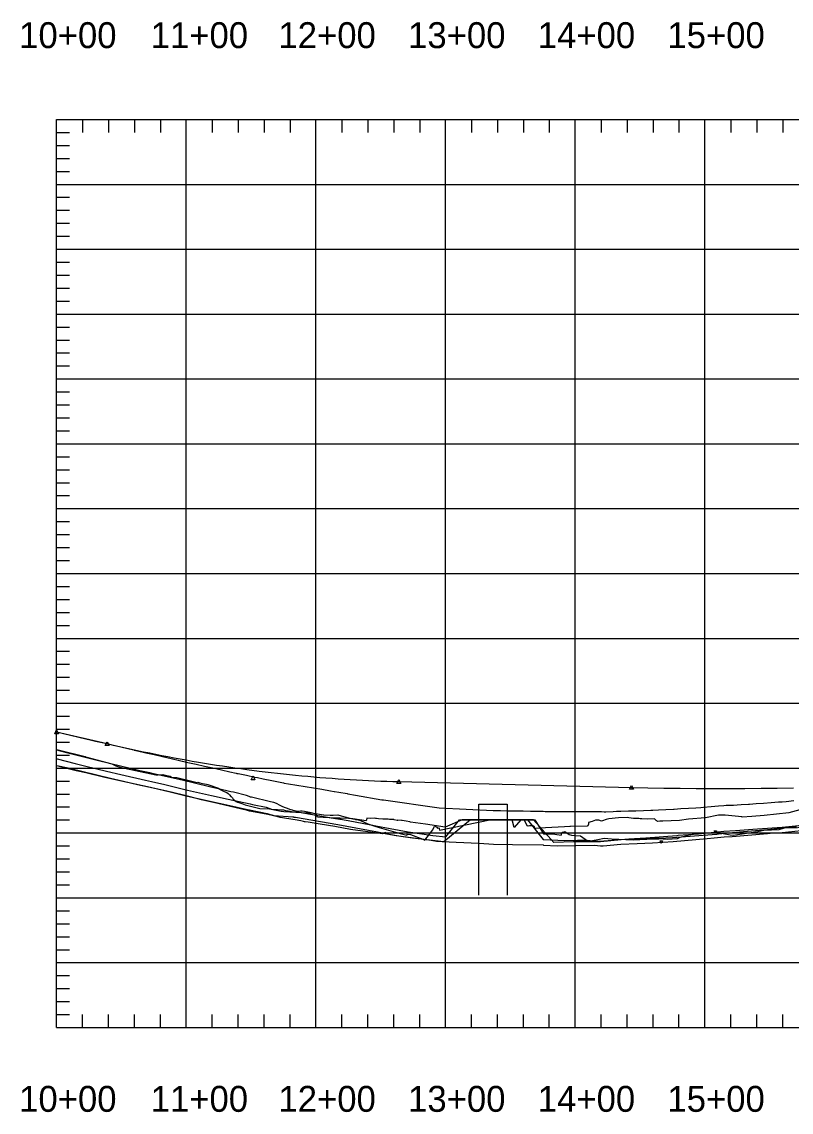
# Model space of a CAD drawing. Extents: x 704797 to 712284, y 374940 to 376945.
# Drawn here: x 708107 to 708700, y 375160 to 376001 of the extents above; entities that cross this region are included whole.
import ezdxf

# ---------------------------------------------------------------- set-up
doc = ezdxf.new("R2010")
doc.units = 0
for name, color, linetype in [('10', 7, 'Continuous'), ('12', 7, 'Continuous'), ('13', 7, 'Continuous'), ('48', 7, 'Continuous'), ('59', 7, 'Continuous'), ('61', 7, 'Continuous'), ('Existing', 7, 'Continuous')]:
    doc.layers.add(name, color=color, linetype=linetype)

msp = doc.modelspace()

# ---------------------------------------------------------------- linework, layer by layer
for points in [[(708133.69, 375454.97), (708135.19, 375451.97), (708132.19, 375451.97)], [(708172.67, 375445.81), (708174.17, 375442.81), (708171.17, 375442.81)], [(708285.17, 375419.37), (708286.67, 375416.37), (708283.67, 375416.37)], [(708397.67, 375416.56), (708399.17, 375413.56), (708396.17, 375413.56)], [(708577.04, 375412.08), (708578.54, 375409.08), (708575.54, 375409.08)]]:
    msp.add_lwpolyline(points, close=True)
at = {"layer": '10'}
for points in [[(708133.69, 375439.73), (708134.76, 375439.47), (708155.61, 375434.31), (708155.61, 375434.31), (708155.66, 375434.3), (708155.98, 375434.22), (708176.28, 375428.84), (708179.34, 375427.13), (708182.39, 375426.07), (708210.14, 375420.26), (708212.04, 375420.15), (708215.59, 375420.47), (708216.24, 375420.32), (708221.15, 375419.28), (708222.3, 375418.47), (708226.34, 375418.16), (708241.94, 375414.47), (708242.59, 375414.52), (708244.15, 375414), (708246.24, 375413.5), (708249.33, 375413.04), (708250.42, 375412.8), (708258.47, 375409.87), (708259.35, 375409.33), (708260.9, 375408.42), (708262.5, 375407.6), (708264.18, 375406.83), (708265, 375406.52), (708265.94, 375405.83), (708265.94, 375405.82), (708266.94, 375404.86), (708267.07, 375404.74), (708268.06, 375403.67), (708268.24, 375403.5), (708269.22, 375402.41), (708269.93, 375401.6), (708270.55, 375401.03), (708271.12, 375400.42), (708272.09, 375399.6), (708272.69, 375399.44), (708273.08, 375399.27), (708273.51, 375399.08), (708276.41, 375398.04), (708279.06, 375397.06), (708290.46, 375394.38), (708297.87, 375394.05), (708306.84, 375392.26), (708307.08, 375392.18), (708307.81, 375392.17), (708308.97, 375391.99), (708331.72, 375390.71), (708339.62, 375389.37), (708339.71, 375389.36), (708344.75, 375389.22), (708346.96, 375389.15), (708350.63, 375389.48), (708353.13, 375388.72), (708362.08, 375386.4), (708362.97, 375386.23), (708363.62, 375385.96), (708364.13, 375385.85), (708365.14, 375385.7), (708366.17, 375385.46), (708367.97, 375385.13), (708373.67, 375382.49), (708379.22, 375380.66), (708382.55, 375379.59), (708394.93, 375376.12), (708399.74, 375374.83), (708403.87, 375373.68), (708404.35, 375374.46), (708406.66, 375374.26), (708416.18, 375370.6), (708417.75, 375369.99), (708423.72, 375377.78), (708425.07, 375380.6), (708427.06, 375379.94), (708427.24, 375379.04), (708428.49, 375379.28), (708428.63, 375379.15), (708428.73, 375378.94), (708428.88, 375377.56), (708467.92, 375385.47), (708502.56, 375385.47), (708509.27, 375374.88), (708518.03, 375374.57), (708522.92, 375373.81), (708523.34, 375375.43), (708523.77, 375376.13), (708524.36, 375376.02), (708525.71, 375376.64), (708528.99, 375374.37), (708530.85, 375373.63), (708533.58, 375373.54), (708537.78, 375373.12), (708543.02, 375369.34), (708546.99, 375369.68), (708551.22, 375370.29), (708556.01, 375371.41), (708561.7, 375370.97), (708578.43, 375370.22), (708589, 375370.55), (708598.16, 375371.04), (708598.39, 375371.05), (708604.7, 375370.79), (708612.65, 375371.23), (708614.53, 375372.14), (708623.8, 375374.49), (708627.82, 375374.94), (708643.39, 375376.09), (708647.69, 375375.08), (708653.26, 375373.97), (708655.37, 375373.74), (708674.49, 375376.61), (708679.08, 375377.54), (708691.09, 375378.17), (708695.19, 375379.52), (708715.38, 375379.96)], [(708715.31, 375395.49), (708698.44, 375391.04), (708679.27, 375388.8), (708669.77, 375388.06), (708662.47, 375387.69), (708662.05, 375387.83), (708649.33, 375389.29), (708645.46, 375389.29), (708644.75, 375389.2), (708644.28, 375389.12), (708634.22, 375387.2), (708621.16, 375386), (708614.04, 375385.15), (708601.26, 375384.58), (708599.05, 375384.46), (708597.12, 375384.35), (708596.73, 375384.68), (708596.17, 375385.04), (708595.73, 375385.27), (708594.9, 375386.27), (708589.46, 375386.18), (708589.43, 375386.18), (708585.05, 375386.37), (708583.67, 375386.45), (708582.63, 375386.49), (708579.54, 375386.55), (708578.61, 375386.54), (708575.1, 375387.21), (708574.98, 375387.2), (708574.08, 375387.29), (708567.06, 375387.06), (708566.99, 375387.03), (708559.61, 375386.34), (708557.61, 375385.77), (708554.7, 375384.86), (708553.84, 375384.6), (708551.96, 375385.43), (708549.23, 375385.21), (708546.67, 375384.34), (708544, 375383.42), (708543.78, 375382.31), (708543.49, 375380.83), (708542.9, 375380.62), (708530.03, 375380.32), (708529.52, 375380.31), (708525.52, 375380.18), (708505.77, 375379.09), (708503.24, 375379.01), (708502.6, 375379.26), (708502.55, 375379.27), (708502.25, 375380.16), (708501.76, 375380.78), (708500.3, 375380.84), (708498.9, 375380.87), (708498.47, 375380.88), (708497.45, 375380.69), (708496.86, 375380.59), (708494.26, 375385.47), (708493.75, 375385.47), (708493.25, 375385.47), (708492.78, 375385.47), (708492.44, 375385.47), (708492.34, 375385.47), (708491.68, 375385.47), (708486.45, 375379.69), (708485.13, 375385.47), (708483.66, 375385.47), (708482.96, 375385.47), (708482.26, 375385.47), (708480.13, 375385.47), (708470.9, 375385.47), (708456.29, 375385.47), (708446.43, 375385.47), (708433.3, 375379.83), (708433.25, 375379.82), (708418.07, 375382.11), (708406.74, 375383.82), (708406.15, 375383.91), (708403.38, 375384.42), (708400.09, 375384.97), (708400, 375384.99), (708399.76, 375385.03), (708396.81, 375385.31), (708396.58, 375385.14), (708396.43, 375385.14), (708394.07, 375385.69), (708393.71, 375385.72), (708393.44, 375385.76), (708390.68, 375385.91), (708390.55, 375385.93), (708390.46, 375385.95), (708389.51, 375386.03), (708389.13, 375386.03), (708387.57, 375386.05), (708387.45, 375386.05), (708385.39, 375386.05), (708381.97, 375386.37), (708380.38, 375386.55), (708379.49, 375386.63), (708378.62, 375386.78), (708376.1, 375386.6), (708375.92, 375386.6), (708372.99, 375386.96), (708372.65, 375385.69), (708372.38, 375384.87), (708362.14, 375386.21), (708358.85, 375386.64), (708352.06, 375386.79), (708351.39, 375386.77), (708350.46, 375386.78), (708349.16, 375386.82), (708347.25, 375386.89), (708344.31, 375387.03), (708339.31, 375387.29), (708334.89, 375387.52), (708334.62, 375388.13), (708334.28, 375388.77), (708333.82, 375390.04), (708330.06, 375390.91), (708324.8, 375391.95), (708322.97, 375392.16), (708322.11, 375392.14), (708321.78, 375392.13), (708319.48, 375391.97), (708318.95, 375392.08), (708318.43, 375392.25), (708316.24, 375392.79), (708315.64, 375393), (708313.61, 375393.57), (708312.96, 375393.83), (708310.97, 375394.47), (708310.31, 375394.74), (708308.26, 375395.63), (708305.98, 375396.73), (708303.19, 375398.21), (708301.32, 375399.02), (708298.67, 375399.56), (708284.03, 375402.92), (708283.25, 375403.16), (708282.26, 375403.52), (708280.09, 375404.24), (708270, 375406.78), (708268.14, 375407.19), (708264.91, 375407.85), (708260.58, 375408.88), (708251.7, 375411.01), (708230.55, 375416.13), (708208.39, 375421.03), (708205.55, 375421.7), (708197.84, 375423.44), (708175.57, 375428.71), (708163.96, 375431.67), (708142.32, 375437.07), (708134.39, 375438.99)]]:
    msp.add_lwpolyline(points, dxfattribs=at)
at = {"layer": '12'}
for points in [[(708133.69, 375432.68), (708134.02, 375432.59), (708148.08, 375428.91), (708156.15, 375426.96), (708172.11, 375423.11), (708183.26, 375420.44), (708202.2, 375416.19), (708206.78, 375415.19), (708217.25, 375412.76), (708234.55, 375408.41), (708253.22, 375404.37), (708265.87, 375401.49), (708282.9, 375398), (708284.83, 375397.5), (708295.34, 375395.24), (708297.44, 375394.55), (708299.44, 375393.84), (708299.66, 375393.82), (708308.6, 375393.21), (708310.14, 375392.84), (708311.33, 375392.61), (708312.34, 375392.45), (708313.2, 375392.31), (708313.91, 375392.18), (708314.5, 375392.04), (708320.64, 375391.6), (708345.42, 375387.16), (708350.63, 375386.4), (708351.32, 375386.31), (708352.13, 375386.2), (708353.08, 375386.06), (708354.17, 375385.88), (708355.47, 375385.66), (708356.95, 375385.39), (708358.65, 375385.07), (708376.14, 375381.72), (708377.68, 375381.44), (708379.84, 375381.03), (708390.95, 375378.92), (708404.72, 375376.29), (708415.31, 375374.83), (708423.93, 375373.56), (708433.76, 375372.55), (708444.47, 375385.47), (708445.33, 375385.47), (708468.35, 375385.47), (708470.13, 375385.47), (708496.9, 375385.47), (708509.01, 375370.49), (708509.22, 375370.32), (708525.68, 375369.67), (708535.51, 375369.87), (708542.67, 375369.91), (708542.81, 375369.91), (708549.73, 375369.2), (708552.77, 375369.13), (708575.08, 375370.92), (708588, 375371.61), (708612.07, 375373.53), (708612.99, 375373.62), (708628.75, 375374.81), (708648.3, 375376.79), (708657.22, 375377.28), (708670.59, 375378.5), (708674.2, 375378.72), (708693.31, 375380.02), (708716.04, 375382.23)], [(708133.69, 375427.41), (708148.65, 375423.72), (708156.15, 375421.96), (708170.91, 375418.5), (708184.72, 375415.29), (708203.76, 375411.15), (708220.29, 375407.32), (708233.71, 375403.95), (708248.56, 375400.73), (708267.15, 375396.49), (708280.97, 375393.65), (708282.56, 375393.24), (708296.05, 375390.33), (708297.61, 375390.02), (708299.55, 375389.44), (708301.32, 375388.87), (708315.75, 375387.9), (708316.05, 375387.84), (708316.28, 375387.79), (708316.47, 375387.77), (708316.63, 375387.74), (708316.76, 375387.72), (708316.86, 375387.7), (708317.91, 375387.63), (708350.44, 375382.01), (708350.52, 375382), (708350.53, 375382), (708350.54, 375382), (708350.56, 375382), (708350.57, 375381.99), (708350.59, 375381.99), (708350.61, 375381.99), (708350.63, 375381.98), (708381.27, 375376.22), (708382.41, 375376), (708388.27, 375374.9), (708395.49, 375373.52), (708422.66, 375369.78), (708426.55, 375369.21), (708430.96, 375368.76), (708441.77, 375368.35), (708459.24, 375367.49), (708459.57, 375367.47), (708470.52, 375366.92), (708485.24, 375366.56), (708509, 375366.22), (708509.12, 375366.12), (708519.62, 375365.63), (708548.44, 375365.95), (708548.54, 375365.95), (708553.12, 375365.52), (708555.09, 375365.49), (708568.92, 375366.69), (708581.41, 375367.43), (708593.17, 375367.87), (708609.3, 375368.92), (708635.35, 375371.06), (708640.95, 375371.66), (708648.48, 375372.38), (708654.71, 375372.69), (708682, 375375.01), (708683.97, 375375.19), (708693.32, 375375.9), (708708.03, 375377.45)]]:
    msp.add_lwpolyline(points, dxfattribs=at)
for points in [[(708641.73, 375375.12), (708640.73, 375377.12), (708642.73, 375377.12)], [(708600.06, 375367.32), (708599.06, 375369.32), (708601.06, 375369.32)]]:
    msp.add_lwpolyline(points, close=True, dxfattribs=at)
at = {"layer": '13'}
msp.add_lwpolyline([(708704.38, 375380.21), (708689.31, 375378.72), (708682.01, 375377.86), (708660.47, 375376.08), (708644.16, 375374.53), (708642.99, 375374.33), (708632.24, 375373.45), (708608.63, 375371.72), (708598.12, 375371.25), (708595.67, 375371.27), (708595.53, 375371.32), (708590.46, 375371.13), (708583.47, 375370.8), (708569.07, 375370.17), (708553.09, 375368.63), (708549.99, 375368.62), (708532.43, 375368.5), (708517.04, 375368.09), (708501.37, 375385.47), (708493.22, 375385.47), (708484.06, 375385.47), (708479.9, 375385.47), (708478.58, 375385.47), (708473.17, 375385.47), (708461.25, 375385.47), (708452.91, 375385.47), (708432.27, 375368.56), (708408.28, 375371.35), (708399.09, 375372.68), (708390.07, 375374.27), (708387.12, 375375.77), (708384.97, 375374.75), (708383.3, 375374.92), (708360.4, 375378.22), (708348.14, 375380.39), (708336.94, 375382.32), (708327.72, 375383.68), (708325.46, 375383.96), (708324.88, 375384.12), (708324.14, 375384.29), (708323.14, 375384.49), (708321.9, 375384.74), (708320.54, 375385), (708319.16, 375385.28), (708309.37, 375386.78), (708307.81, 375387.13), (708306.15, 375387.49), (708304.36, 375387.88), (708296.49, 375389.61), (708284.04, 375392.04), (708282.49, 375392.22), (708280.87, 375392.65), (708263.53, 375396.86), (708258.09, 375398.21), (708245.51, 375400.97), (708242.67, 375401.7), (708240.48, 375402.26), (708235.54, 375403.53), (708230.43, 375404.8), (708218.65, 375407.56), (708208.21, 375409.9), (708196.14, 375412.65), (708185.25, 375415.24), (708175.23, 375417.54), (708164.63, 375420.1), (708153.21, 375422.78), (708145.66, 375424.55), (708142.6, 375425.27), (708133.88, 375427.31)], dxfattribs=at)
at = {"layer": '48'}
for p, q in [((708133.69, 375453.47), (708172.67, 375444.31)), ((708397.67, 375415.06), (708577.04, 375410.58))]:
    msp.add_line(p, q, dxfattribs=at)
for points in [[(708172.67, 375444.31), (708177.36, 375443.22), (708182.05, 375442.15), (708186.73, 375441.1), (708191.42, 375440.07), (708196.11, 375439.06), (708200.8, 375438.07), (708205.48, 375437.1), (708210.17, 375436.15), (708214.86, 375435.23), (708219.55, 375434.32), (708224.23, 375433.43), (708228.92, 375432.57), (708233.61, 375431.72), (708238.3, 375430.9), (708242.98, 375430.09), (708247.67, 375429.31), (708252.36, 375428.55), (708257.05, 375427.8), (708261.73, 375427.08), (708266.42, 375426.38), (708271.11, 375425.7), (708275.8, 375425.04), (708280.48, 375424.4), (708289.86, 375423.18), (708294.55, 375422.6), (708299.23, 375422.04), (708303.92, 375421.51), (708308.61, 375420.99), (708313.3, 375420.49), (708317.98, 375420.02), (708322.67, 375419.56), (708327.36, 375419.12), (708332.05, 375418.71), (708336.73, 375418.32), (708341.42, 375417.94), (708346.11, 375417.59), (708350.8, 375417.26), (708355.48, 375416.95), (708360.17, 375416.65), (708364.86, 375416.38), (708369.55, 375416.13), (708374.23, 375415.9), (708378.92, 375415.69), (708383.61, 375415.5), (708388.3, 375415.34), (708392.98, 375415.19), (708397.67, 375415.06)], [(708577.04, 375410.58), (708589.54, 375410.29), (708602.04, 375410.06), (708614.54, 375409.89), (708627.04, 375409.78), (708639.54, 375409.72), (708652.04, 375409.72), (708664.54, 375409.77), (708677.04, 375409.88), (708689.54, 375410.05), (708702.04, 375410.27)]]:
    msp.add_lwpolyline(points, dxfattribs=at)
at = {"layer": '59'}
msp.add_lwpolyline([(708459.24, 375327.55), (708459.25, 375379.33), (708459.26, 375397.55), (708468.78, 375397.63), (708470.26, 375397.65), (708470.29, 375397.65), (708476.09, 375397.59), (708477.63, 375397.58), (708480.65, 375397.55), (708481.27, 375397.55), (708481.27, 375392.88), (708481.29, 375327.55)], dxfattribs=at)
at = {"layer": '61'}
for p, q in [((708133.69, 375925.47), (712133.69, 375925.47)), ((708133.69, 375225.47), (708133.69, 375925.47)), ((708153.69, 375925.47), (708153.69, 375915.47)), ((708173.69, 375925.47), (708173.69, 375915.47)), ((708193.69, 375925.47), (708193.69, 375915.47)), ((708213.69, 375925.47), (708213.69, 375915.47)), ((708233.69, 375225.47), (708233.69, 375925.47)), ((708253.69, 375925.47), (708253.69, 375915.47)), ((708273.69, 375925.47), (708273.69, 375915.47)), ((708293.69, 375925.47), (708293.69, 375915.47)), ((708313.69, 375925.47), (708313.69, 375915.47)), ((708333.69, 375225.47), (708333.69, 375925.47)), ((708353.69, 375925.47), (708353.69, 375915.47)), ((708373.69, 375925.47), (708373.69, 375915.47)), ((708393.69, 375925.47), (708393.69, 375915.47)), ((708413.69, 375925.47), (708413.69, 375915.47)), ((708433.69, 375225.47), (708433.69, 375925.47)), ((708453.69, 375925.47), (708453.69, 375915.47)), ((708473.69, 375925.47), (708473.69, 375915.47)), ((708493.69, 375925.47), (708493.69, 375915.47)), ((708513.69, 375925.47), (708513.69, 375915.47)), ((708533.69, 375225.47), (708533.69, 375925.47)), ((708553.69, 375925.47), (708553.69, 375915.47)), ((708573.69, 375925.47), (708573.69, 375915.47)), ((708593.69, 375925.47), (708593.69, 375915.47)), ((708613.69, 375925.47), (708613.69, 375915.47)), ((708633.69, 375225.47), (708633.69, 375925.47)), ((708653.69, 375925.47), (708653.69, 375915.47)), ((708673.69, 375925.47), (708673.69, 375915.47)), ((708693.69, 375925.47), (708693.69, 375915.47)), ((708133.69, 375915.47), (708143.69, 375915.47)), ((708133.69, 375905.47), (708143.69, 375905.47)), ((708133.69, 375895.47), (708143.69, 375895.47)), ((708133.69, 375885.47), (708143.69, 375885.47)), ((708133.69, 375875.47), (712133.69, 375875.47)), ((708133.69, 375865.47), (708143.69, 375865.47)), ((708133.69, 375855.47), (708143.69, 375855.47)), ((708133.69, 375845.47), (708143.69, 375845.47)), ((708133.69, 375835.47), (708143.69, 375835.47)), ((708133.69, 375825.47), (712133.69, 375825.47)), ((708133.69, 375815.47), (708143.69, 375815.47)), ((708133.69, 375805.47), (708143.69, 375805.47)), ((708133.69, 375795.47), (708143.69, 375795.47)), ((708133.69, 375785.47), (708143.69, 375785.47)), ((708133.69, 375775.47), (712133.69, 375775.47)), ((708133.69, 375765.47), (708143.69, 375765.47)), ((708133.69, 375755.47), (708143.69, 375755.47)), ((708133.69, 375745.47), (708143.69, 375745.47)), ((708133.69, 375735.47), (708143.69, 375735.47)), ((708133.69, 375725.47), (712133.69, 375725.47)), ((708133.69, 375715.47), (708143.69, 375715.47)), ((708133.69, 375705.47), (708143.69, 375705.47)), ((708133.69, 375695.47), (708143.69, 375695.47)), ((708133.69, 375685.47), (708143.69, 375685.47)), ((708133.69, 375675.47), (712133.69, 375675.47)), ((708133.69, 375665.47), (708143.69, 375665.47)), ((708133.69, 375655.47), (708143.69, 375655.47)), ((708133.69, 375645.47), (708143.69, 375645.47)), ((708133.69, 375635.47), (708143.69, 375635.47)), ((708133.69, 375625.47), (712133.69, 375625.47)), ((708133.69, 375615.47), (708143.69, 375615.47)), ((708133.69, 375605.47), (708143.69, 375605.47)), ((708133.69, 375595.47), (708143.69, 375595.47)), ((708133.69, 375585.47), (708143.69, 375585.47)), ((708133.69, 375575.47), (712133.69, 375575.47)), ((708133.69, 375565.47), (708143.69, 375565.47)), ((708133.69, 375555.47), (708143.69, 375555.47)), ((708133.69, 375545.47), (708143.69, 375545.47)), ((708133.69, 375535.47), (708143.69, 375535.47)), ((708133.69, 375525.47), (712133.69, 375525.47)), ((708133.69, 375515.47), (708143.69, 375515.47)), ((708133.69, 375505.47), (708143.69, 375505.47)), ((708133.69, 375495.47), (708143.69, 375495.47)), ((708133.69, 375485.47), (708143.69, 375485.47)), ((708133.69, 375475.47), (712133.69, 375475.47)), ((708133.69, 375465.47), (708143.69, 375465.47)), ((708133.69, 375455.47), (708143.69, 375455.47)), ((708133.69, 375445.47), (708143.69, 375445.47)), ((708133.69, 375435.47), (708143.69, 375435.47)), ((708133.69, 375425.47), (712133.69, 375425.47)), ((708133.69, 375415.47), (708143.69, 375415.47)), ((708133.69, 375405.47), (708143.69, 375405.47)), ((708133.69, 375395.47), (708143.69, 375395.47)), ((708133.69, 375385.47), (708143.69, 375385.47)), ((708133.69, 375375.47), (712133.69, 375375.47)), ((708133.69, 375365.47), (708143.69, 375365.47)), ((708133.69, 375355.47), (708143.69, 375355.47)), ((708133.69, 375345.47), (708143.69, 375345.47)), ((708133.69, 375335.47), (708143.69, 375335.47)), ((708133.69, 375325.47), (712133.69, 375325.47)), ((708133.69, 375315.47), (708143.69, 375315.47)), ((708133.69, 375305.47), (708143.69, 375305.47)), ((708133.69, 375295.47), (708143.69, 375295.47)), ((708133.69, 375285.47), (708143.69, 375285.47)), ((708133.69, 375275.47), (712133.69, 375275.47)), ((708133.69, 375265.47), (708143.69, 375265.47)), ((708133.69, 375255.47), (708143.69, 375255.47)), ((708133.69, 375245.47), (708143.69, 375245.47)), ((708133.69, 375235.47), (708143.69, 375235.47)), ((708153.69, 375225.47), (708153.69, 375235.47)), ((708173.69, 375225.47), (708173.69, 375235.47)), ((708193.69, 375225.47), (708193.69, 375235.47)), ((708213.69, 375225.47), (708213.69, 375235.47)), ((708253.69, 375225.47), (708253.69, 375235.47)), ((708273.69, 375225.47), (708273.69, 375235.47)), ((708293.69, 375225.47), (708293.69, 375235.47)), ((708313.69, 375225.47), (708313.69, 375235.47)), ((708353.69, 375225.47), (708353.69, 375235.47)), ((708373.69, 375225.47), (708373.69, 375235.47)), ((708393.69, 375225.47), (708393.69, 375235.47)), ((708413.69, 375225.47), (708413.69, 375235.47)), ((708453.69, 375225.47), (708453.69, 375235.47)), ((708473.69, 375225.47), (708473.69, 375235.47)), ((708493.69, 375225.47), (708493.69, 375235.47)), ((708513.69, 375225.47), (708513.69, 375235.47)), ((708553.69, 375225.47), (708553.69, 375235.47)), ((708573.69, 375225.47), (708573.69, 375235.47)), ((708593.69, 375225.47), (708593.69, 375235.47)), ((708613.69, 375225.47), (708613.69, 375235.47)), ((708653.69, 375225.47), (708653.69, 375235.47)), ((708673.69, 375225.47), (708673.69, 375235.47)), ((708693.69, 375225.47), (708693.69, 375235.47)), ((708133.69, 375225.47), (712133.69, 375225.47))]:
    msp.add_line(p, q, dxfattribs=at)
at = {"layer": 'Existing'}
msp.add_lwpolyline([(708133.69, 375453.38), (708144.27, 375450.89), (708150.74, 375449.36), (708157.21, 375447.83), (708157.39, 375447.79), (708157.44, 375447.77), (708157.48, 375447.76), (708163.67, 375446.32), (708170.13, 375444.82), (708170.14, 375444.82), (708170.17, 375444.81), (708176.61, 375443.31), (708183.08, 375441.8), (708189.55, 375440.29), (708193.14, 375439.45), (708193.28, 375439.42), (708193.43, 375439.38), (708196.02, 375438.79), (708202.49, 375437.31), (708208.96, 375435.83), (708215.43, 375434.34), (708221.9, 375432.85), (708228.37, 375431.36), (708230.52, 375430.87), (708230.67, 375430.83), (708230.74, 375430.81), (708230.81, 375430.8), (708230.87, 375430.78), (708234.84, 375429.89), (708241.31, 375428.45), (708247.77, 375427), (708254.24, 375425.55), (708260.71, 375424.09), (708267.18, 375422.64), (708272.08, 375421.53), (708272.22, 375421.49), (708272.66, 375421.38), (708272.7, 375421.37), (708272.74, 375421.37), (708273.65, 375421.18), (708280.12, 375419.88), (708286.59, 375418.56), (708288.61, 375418.15), (708293.06, 375417.23), (708299.53, 375415.89), (708306, 375414.55), (708308.7, 375413.99), (708308.73, 375413.98), (708308.76, 375413.97), (708309.05, 375413.95), (708312.47, 375413.39), (708318.94, 375412.32), (708325.41, 375411.24), (708331.87, 375410.17), (708338.34, 375409.1), (708344.81, 375408.03), (708347.85, 375407.52), (708348.05, 375407.49), (708351.28, 375406.92), (708357.75, 375405.79), (708358.29, 375405.7), (708364.22, 375404.65), (708384.6, 375401.04), (708385.24, 375400.95), (708385.28, 375400.95), (708385.34, 375400.97), (708385.42, 375400.93), (708385.66, 375400.89), (708428.69, 375394.74), (708470.29, 375392.8), (708470.92, 375392.77), (708470.92, 375392.77), (708470.92, 375392.77), (708470.92, 375392.77), (708476.09, 375392.71), (708481.88, 375392.63), (708487.68, 375392.55), (708493.48, 375392.46), (708499.27, 375392.37), (708505.07, 375392.26), (708508.99, 375392.19), (708509, 375392.18), (708510.53, 375392.1), (708510.87, 375392.1), (708516.66, 375392.11), (708522.46, 375392.11), (708528.26, 375392.11), (708534.05, 375392.09), (708539.85, 375392.06), (708545.65, 375392.01), (708551.44, 375391.96), (708553.83, 375391.94), (708553.87, 375391.94), (708556.01, 375391.66), (708556.99, 375391.61), (708557.24, 375391.63), (708563.04, 375391.98), (708565.51, 375392.12), (708568.83, 375392.23), (708574.63, 375392.42), (708580.43, 375392.6), (708586.22, 375392.77), (708592.02, 375392.93), (708593.56, 375392.97), (708597.82, 375393.2), (708603.61, 375393.51), (708609.41, 375393.81), (708609.92, 375393.83), (708615.21, 375394.18), (708621, 375394.55), (708626.8, 375394.91), (708630.44, 375395.13), (708632.6, 375395.32), (708638.39, 375395.83), (708644.19, 375396.33), (708648.27, 375396.68), (708649.99, 375396.75), (708655.78, 375396.97), (708658.53, 375397.07), (708661.58, 375397.28), (708667.38, 375397.67), (708668.09, 375397.71), (708673.17, 375398.09), (708678.97, 375398.51), (708684.77, 375398.92), (708690.56, 375399.32), (708693.3, 375399.51), (708696.36, 375399.8), (708702.16, 375400.36)], dxfattribs=at)

# ---------------------------------------------------------------- texts
at = {"layer": '61'}
for s, p in [('10+00', (708104.77, 375980.47)), ('11+00', (708206.21, 375980.47)), ('12+00', (708304.77, 375980.47)), ('13+00', (708404.77, 375980.47)), ('14+00', (708504.77, 375980.47)), ('15+00', (708604.77, 375980.47)), ('10+00', (708104.77, 375160.47)), ('11+00', (708206.21, 375160.47)), ('12+00', (708304.77, 375160.47)), ('13+00', (708404.77, 375160.47)), ('14+00', (708504.77, 375160.47)), ('15+00', (708604.77, 375160.47))]:
    msp.add_text(s, height=20, dxfattribs=at).set_placement(p)

doc.saveas('drawing.dxf')
